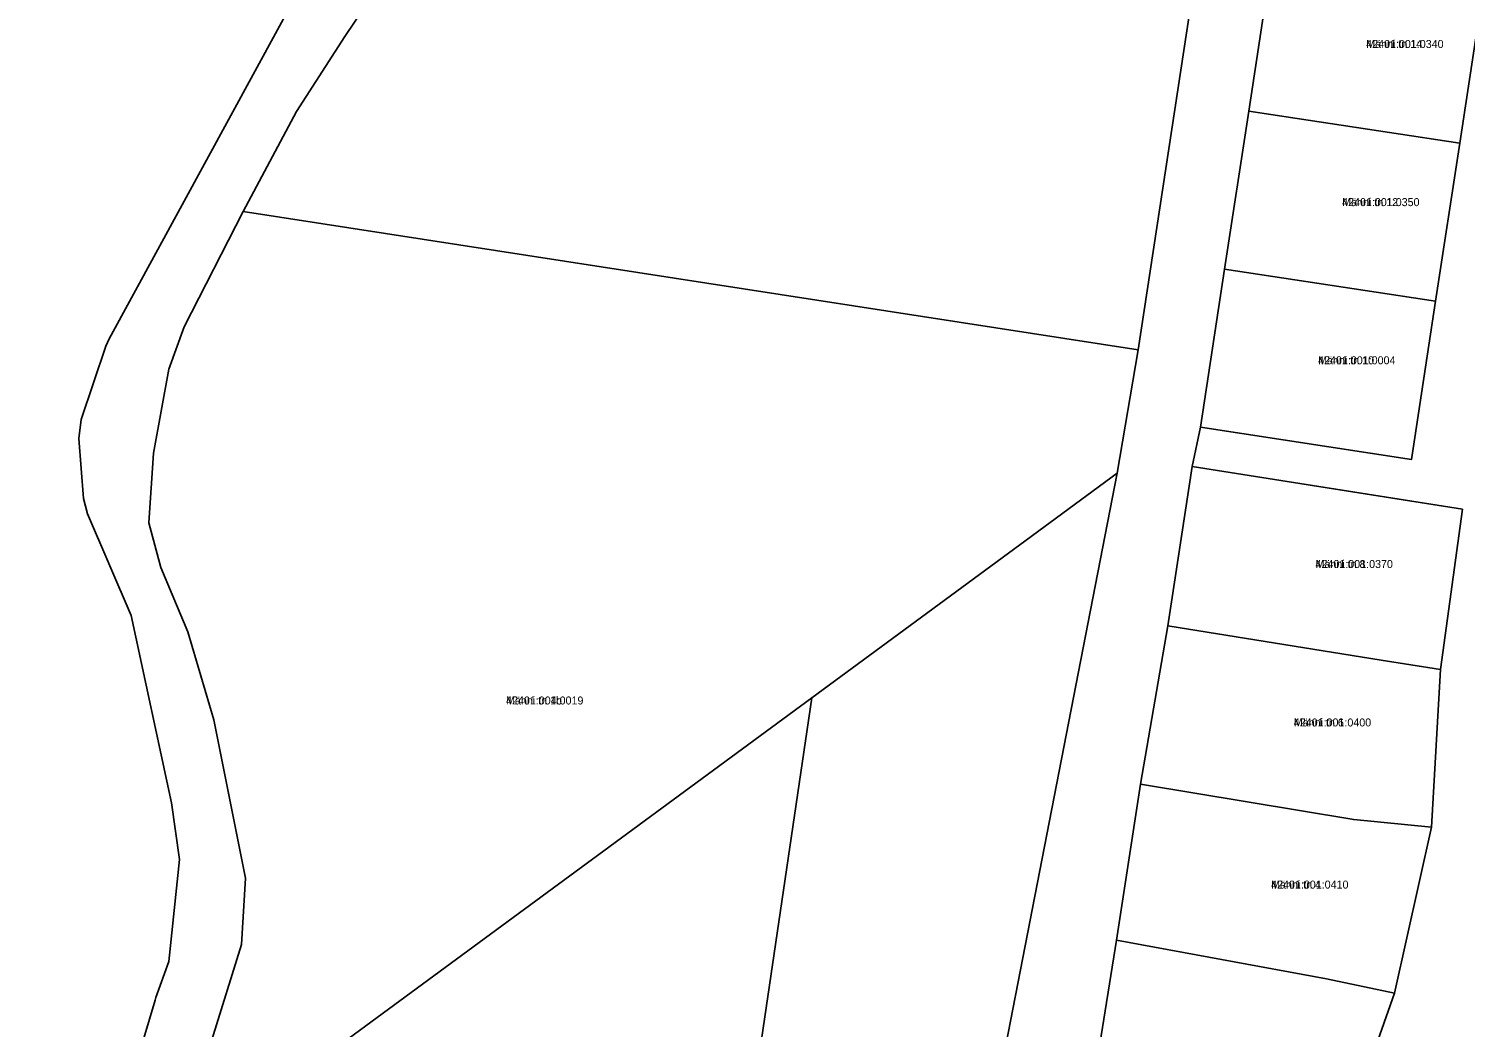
# Model space of a CAD drawing. Extents: x 595979 to 597983, y 6604231 to 6607350.
# Drawn here: x 596596.1 to 596865.4, y 6605281.9 to 6605469.2 of the extents above; entities that cross this region are included whole.
import ezdxf

# ---------------------------------------------------------------- set-up
doc = ezdxf.new("R2010")
doc.units = 0
for name, color, linetype in [('L_AADRESS', 7, 'Continuous'), ('PIIR', 7, 'Continuous'), ('TUNNUS', 7, 'Continuous')]:
    doc.layers.add(name, color=color, linetype=linetype)

msp = doc.modelspace()

# ---------------------------------------------------------------- linework, layer by layer
at = {"layer": 'PIIR'}
for points in [[(596707.32, 6605548), (596720.74, 6605540.34), (596740.22, 6605537.04), (596736.33, 6605515.61), (596785.62, 6605497.09), (596799.33, 6605491.84), (596806.33, 6605564.68), (596806.93, 6605570.9), (596828.15, 6605567.17), (596804.06, 6605408.95), (596636.26, 6605434.88), (596646.27, 6605453.64), (596655.33, 6605467.74), (596693.66, 6605524.62)], [(596868.82, 6605477.39), (596864.31, 6605447.73), (596824.76, 6605453.75), (596829.27, 6605483.41)], [(596864.31, 6605447.73), (596859.8, 6605418.07), (596820.25, 6605424.09), (596824.76, 6605453.75)], [(596636.26, 6605434.88), (596804.06, 6605408.95), (596800.12, 6605385.84), (596781.86, 6605372.4), (596701.75, 6605313.42), (596615.57, 6605250.02), (596630.39, 6605279.58), (596635.95, 6605297.46), (596636.74, 6605309.9), (596630.78, 6605339.55), (596625.88, 6605356.1), (596620.85, 6605368.15), (596618.6, 6605376.49), (596619.44, 6605389.57), (596622.31, 6605405.35), (596625.22, 6605413.29)], [(596859.8, 6605418.07), (596855.3, 6605388.41), (596815.74, 6605394.45), (596820.25, 6605424.09)], [(596814.19, 6605387.1), (596853.72, 6605380.83), (596864.82, 6605379.06), (596860.74, 6605348.98), (596849.56, 6605350.77), (596809.6, 6605357.21)], [(596611.84, 6605088.12), (596615.27, 6605108.65), (596615.29, 6605108.8), (596620.49, 6605143.43), (596620.57, 6605144.18), (596621.36, 6605156.21), (596723.1, 6605209.62), (596742.88, 6605343.7), (596781.86, 6605372.4), (596800.12, 6605385.84), (596765.64, 6605208.57), (596754.93, 6605167.57), (596732.37, 6605155.68)], [(596809.6, 6605357.21), (596849.56, 6605350.77), (596860.74, 6605348.98), (596859, 6605319.44), (596844.45, 6605320.85), (596804.47, 6605327.52)], [(596701.75, 6605313.42), (596742.88, 6605343.7), (596723.1, 6605209.62), (596621.36, 6605156.21), (596620.94, 6605176.05), (596619.36, 6605195.41), (596615.57, 6605250.02)], [(596804.47, 6605327.52), (596844.45, 6605320.85), (596859, 6605319.44), (596852.1, 6605288.33), (596839.35, 6605290.97), (596800, 6605298.23)], [(596800, 6605298.23), (596839.35, 6605290.97), (596852.1, 6605288.33), (596844.57, 6605267.01), (596834.44, 6605261.91), (596792.47, 6605252.09), (596795.25, 6605268.62)]]:
    msp.add_lwpolyline(points, close=True, dxfattribs=at)
for points in [[(596829.27, 6605483.41), (596824.76, 6605453.75), (596820.25, 6605424.09), (596815.74, 6605394.45), (596814.19, 6605387.1), (596809.6, 6605357.21), (596804.47, 6605327.52), (596800, 6605298.23), (596795.25, 6605268.62), (596792.47, 6605252.09), (596788.8, 6605231.98), (596790.07, 6605229.75), (596789.19, 6605229.26), (596781.93, 6605213.04), (596789.19, 6605184.96), (596754.93, 6605167.57), (596765.64, 6605208.57), (596800.12, 6605385.84), (596804.06, 6605408.95), (596828.15, 6605567.17)], [(596693.66, 6605524.62), (596655.33, 6605467.74), (596646.27, 6605453.64), (596636.26, 6605434.88), (596625.22, 6605413.29), (596622.31, 6605405.35), (596619.44, 6605389.57), (596618.6, 6605376.49), (596620.85, 6605368.15), (596625.88, 6605356.1), (596630.78, 6605339.55), (596636.74, 6605309.9), (596635.95, 6605297.46), (596630.39, 6605279.58)], [(596647.27, 6605477.41), (596611.18, 6605411.05), (596610.56, 6605409.63), (596605.93, 6605395.9), (596605.48, 6605392.31), (596606.36, 6605381.09), (596607.07, 6605378.23), (596615.3, 6605359.14), (596622.82, 6605323.98), (596624.34, 6605313.37), (596622.34, 6605294.27), (596619.91, 6605287.47), (596619.75, 6605287), (596615.72, 6605273.39), (596608.35, 6605259.53), (596607.93, 6605258.6), (596601.78, 6605243.01), (596601.25, 6605241.06), (596600.61, 6605236.85), (596540.44, 6605248.17)], [(596615.72, 6605273.39), (596619.75, 6605287), (596619.91, 6605287.47), (596622.34, 6605294.27), (596624.34, 6605313.37), (596622.82, 6605323.98), (596615.3, 6605359.14), (596607.07, 6605378.23), (596606.36, 6605381.09), (596605.48, 6605392.31), (596605.93, 6605395.9), (596610.56, 6605409.63), (596611.18, 6605411.05), (596647.27, 6605477.41)], [(596877.22, 6605277.92), (596851, 6605263.59), (596870.21, 6605228.44), (596863.33, 6605224.33), (596845.82, 6605256.63), (596843.99, 6605259.57), (596844.57, 6605267.01), (596852.1, 6605288.33), (596859, 6605319.44), (596860.74, 6605348.98), (596864.82, 6605379.06), (596814.19, 6605387.1), (596815.74, 6605394.45), (596855.3, 6605388.41), (596859.8, 6605418.07), (596864.31, 6605447.73), (596868.82, 6605477.39)]]:
    msp.add_lwpolyline(points, dxfattribs=at)

# ---------------------------------------------------------------- texts
at = {"layer": 'L_AADRESS'}
for s, p in [('Männi tn 14', (596846.79, 6605465.57)), ('Männi tn 12', (596842.28, 6605435.91)), ('Männi tn 10', (596837.77, 6605406.25)), ('Männi tn 8', (596837.29, 6605368.04)), ('Männi tn 1b', (596685.55, 6605342.45)), ('Männi tn 6', (596833.22, 6605338.33)), ('Männi tn 4', (596828.96, 6605307.92))]:
    msp.add_text(s, height=1.5, dxfattribs=at).set_placement(p)
at = {"layer": 'TUNNUS'}
for s, p in [('42401:001:0340', (596846.79, 6605465.57)), ('42401:001:0350', (596842.28, 6605435.91)), ('42401:001:0004', (596837.77, 6605406.25)), ('42401:001:0370', (596837.29, 6605368.04)), ('42401:004:0019', (596685.55, 6605342.45)), ('42401:001:0400', (596833.22, 6605338.33)), ('42401:001:0410', (596828.96, 6605307.92))]:
    msp.add_text(s, height=1.5, dxfattribs=at).set_placement(p)

doc.saveas('drawing.dxf')
